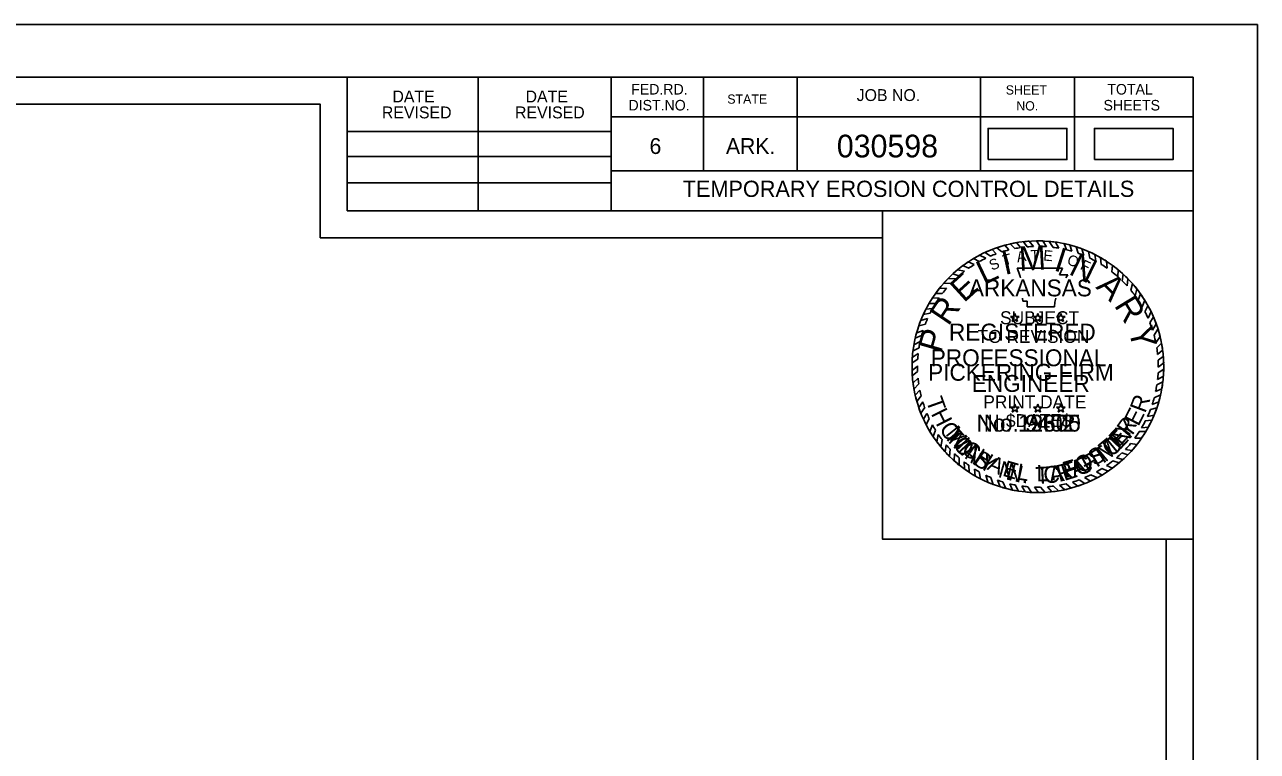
# Model space of a CAD drawing. Extents: x 814841 to 962585, y -174183 to 1802800.
# Drawn here: x 820260 to 820716.4, y 1802531 to 1802800.1 of the extents above; entities that cross this region are included whole.
import ezdxf

# ---------------------------------------------------------------- set-up
doc = ezdxf.new("R2010")
doc.units = 0
for name, color, linetype in [('R_Border', 7, 'Continuous'), ('R_Border Notes', 7, 'Continuous'), ('R_No Plot', 7, 'Continuous'), ('STAMP_PE_CRAFTON', 7, 'Continuous'), ('STAMP_PE_FOSTER', 7, 'Continuous'), ('STAMP_PE_SEAL-INFO', 7, 'Continuous'), ('STAMP_PE_TAEGTMEYER', 7, 'Continuous'), ('STAMP_PE_TXT', 7, 'Continuous'), ('STAMP_PRELIMINARY', 7, 'Continuous'), ('Veg Buffer', 7, 'Continuous')]:
    doc.layers.add(name, color=color, linetype=linetype)

msp = doc.modelspace()

# ---------------------------------------------------------------- linework, layer by layer
at = {"layer": 'R_Border'}
for p, q in [((819111.78, 1802780.6), (820692.68, 1802780.6)), ((820379.48, 1802731.2), (820379.48, 1802780.6)), ((820427.88, 1802731.2), (820427.88, 1802780.6)), ((820477.18, 1802780.6), (820477.18, 1802731.2)), ((820511.38, 1802780.6), (820511.38, 1802745.9)), ((820546.08, 1802780.6), (820546.08, 1802745.9)), ((820613.98, 1802780.6), (820613.98, 1802745.9)), ((820648.68, 1802780.6), (820648.68, 1802745.9)), ((820692.68, 1801753.3), (820692.68, 1802780.6)), ((820692.68, 1802765.9), (820477.18, 1802765.9)), ((820692.68, 1802766), (820692.68, 1802766)), ((820379.48, 1802760.5), (820477.18, 1802760.5)), ((820379.48, 1802751.2), (820477.18, 1802751.2)), ((820692.68, 1802745.9), (820477.18, 1802745.9)), ((820491.98, 1802745.9), (820692.68, 1802745.9)), ((820379.48, 1802741.5), (820477.18, 1802741.5)), ((820692.68, 1802731.2), (820379.48, 1802731.2))]:
    msp.add_line(p, q, dxfattribs=at)
at = {"layer": 'R_No Plot'}
for points in [[(819049.74, 1802800.08), (820716.44, 1802800.08), (820716.44, 1801733.39), (819049.74, 1801733.39)], [(820682.68, 1802276.95), (819121.78, 1802276.95), (819121.78, 1802770.6), (820369.48, 1802770.6), (820369.48, 1802721.2), (820457.18, 1802721.2), (820577.68, 1802721.2), (820577.68, 1802609.54), (820682.68, 1802609.54)], [(820682.68, 1802276.95), (819121.78, 1802276.95), (819121.78, 1802770.6), (820369.48, 1802770.6), (820369.48, 1802721.2), (820457.18, 1802721.2), (820577.68, 1802721.2), (820577.68, 1802609.54), (820682.68, 1802609.54)], [(820682.68, 1802276.95), (819121.78, 1802276.95), (819121.78, 1802770.6), (820369.48, 1802770.6), (820369.48, 1802721.2), (820457.18, 1802721.2), (820577.68, 1802721.2), (820577.68, 1802609.54), (820682.68, 1802609.54)], [(820682.68, 1802276.95), (819121.78, 1802276.95), (819121.78, 1802770.6), (820369.48, 1802770.6), (820369.48, 1802721.2), (820457.18, 1802721.2), (820577.68, 1802721.2), (820577.68, 1802609.54), (820682.68, 1802609.54)], [(820682.68, 1802276.95), (819121.78, 1802276.95), (819121.78, 1802770.6), (820369.48, 1802770.6), (820369.48, 1802721.2), (820457.18, 1802721.2), (820577.68, 1802721.2), (820577.68, 1802609.54), (820682.68, 1802609.54)], [(820682.68, 1802276.95), (819121.78, 1802276.95), (819121.78, 1802770.6), (820369.48, 1802770.6), (820369.48, 1802721.2), (820457.18, 1802721.2), (820577.68, 1802721.2), (820577.68, 1802609.54), (820682.68, 1802609.54)], [(819121.78, 1802770.6), (820369.48, 1802770.6), (820369.48, 1802721.2), (820457.18, 1802721.2), (820577.68, 1802721.2), (820577.68, 1802609.54), (820682.68, 1802609.54), (820682.68, 1801763.3), (819121.78, 1801763.3)], [(820682.68, 1802276.95), (819121.78, 1802276.95), (819121.78, 1802770.6), (820369.48, 1802770.6), (820369.48, 1802721.2), (820457.18, 1802721.2), (820577.68, 1802721.2), (820577.68, 1802609.54), (820682.68, 1802609.54)], [(820577.68, 1802731.2), (820692.68, 1802731.2), (820692.68, 1802609.54), (820577.68, 1802609.54)]]:
    msp.add_lwpolyline(points, close=True, dxfattribs=at)
at = {"layer": 'STAMP_PE_SEAL-INFO'}
for p, q in [((820627.28, 1802719.36), (820628.78, 1802717.52)), ((820629.86, 1802719.72), (820631.27, 1802717.81)), ((820633.54, 1802717.95), (820631.98, 1802719.92)), ((820636.03, 1802717.98), (820634.63, 1802720.03)), ((820638.32, 1802717.87), (820637.03, 1802719.99)), ((820640.85, 1802717.62), (820639.38, 1802719.84)), ((820642.97, 1802717.3), (820641.69, 1802719.57)), ((820645.79, 1802716.7), (820644.92, 1802719)), ((820613.54, 1802714.7), (820615.86, 1802713.58)), ((820615.7, 1802715.76), (820617.65, 1802714.39)), ((820618.24, 1802716.84), (820619.71, 1802715.21)), ((820619.98, 1802717.48), (820621.88, 1802715.95)), ((820622.93, 1802718.39), (820624.37, 1802716.65)), ((820624.87, 1802718.88), (820626.65, 1802717.16)), ((820647.79, 1802716.16), (820647, 1802718.51)), ((820650.05, 1802715.43), (820649.35, 1802717.82)), ((820652.14, 1802714.63), (820651.42, 1802717.11)), ((820654.45, 1802713.6), (820653.94, 1802716.09)), ((820656.68, 1802712.45), (820656.24, 1802715)), ((820607.27, 1802710.9), (820609.55, 1802709.87)), ((820609.37, 1802712.23), (820611.58, 1802711.22)), ((820611.3, 1802713.45), (820613.46, 1802712.34)), ((820627.54, 1802709.87), (820644.26, 1802709.87)), ((820628.15, 1802708.34), (820627.54, 1802709.87)), ((820644.26, 1802709.87), (820643.14, 1802707.41)), ((820658.62, 1802711.32), (820658.42, 1802713.82)), ((820660.79, 1802709.89), (820660.63, 1802712.46)), ((820662.59, 1802708.55), (820662.76, 1802710.99)), ((820601.99, 1802706.14), (820604.71, 1802705.94)), ((820603.66, 1802707.76), (820605.96, 1802707.07)), ((820605.38, 1802709.26), (820608.03, 1802708.76)), ((820628.67, 1802706.85), (820628.15, 1802708.34)), ((820628.71, 1802706.28), (820628.67, 1802706.85)), ((820643.14, 1802707.41), (820646.3, 1802707.41)), ((820646.3, 1802707.41), (820645.58, 1802706.28)), ((820664.83, 1802706.69), (820664.92, 1802709.31)), ((820666.39, 1802705.23), (820666.73, 1802707.72)), ((820668.18, 1802703.36), (820668.52, 1802705.99)), ((820598.65, 1802702.37), (820601.39, 1802702.48)), ((820600.37, 1802704.42), (820602.98, 1802704.23)), ((820669.55, 1802701.78), (820670.23, 1802704.14)), ((820671.17, 1802699.7), (820671.85, 1802702.19)), ((820594.85, 1802696.79), (820597.3, 1802696.89)), ((820596.08, 1802698.8), (820598.66, 1802698.97)), ((820597.25, 1802700.52), (820599.78, 1802700.49)), ((820629.66, 1802697.73), (820629.53, 1802698.82)), ((820631.23, 1802697.73), (820629.66, 1802697.73)), ((820631.23, 1802695.58), (820631.23, 1802697.73)), ((820641.46, 1802697.27), (820641.38, 1802695.58)), ((820641.85, 1802698.82), (820641.46, 1802697.27)), ((820672.27, 1802698.12), (820673.16, 1802700.44)), ((820673.81, 1802695.63), (820674.73, 1802698.09)), ((820592.76, 1802692.73), (820595.27, 1802693.25)), ((820593.7, 1802694.68), (820596.19, 1802695)), ((820641.38, 1802695.58), (820631.23, 1802695.58)), ((820674.81, 1802693.8), (820675.94, 1802696.02)), ((820675.96, 1802691.38), (820677.1, 1802693.81)), ((820676.67, 1802689.7), (820677.99, 1802691.86)), ((820591.09, 1802688.54), (820593.51, 1802689.22)), ((820591.84, 1802690.57), (820594.36, 1802691.3)), ((820677.64, 1802686.95), (820678.99, 1802689.32)), ((820678.18, 1802685.13), (820679.65, 1802687.39)), ((820591.6, 1802682.75), (820589.27, 1802681.51)), ((820589.78, 1802683.99), (820592.13, 1802684.95)), ((820590.3, 1802686.02), (820592.69, 1802686.87)), ((820678.84, 1802682.33), (820680.44, 1802684.57)), ((820590.88, 1802678.28), (820588.69, 1802676.88)), ((820591.17, 1802680.46), (820588.94, 1802679.35)), ((820679.19, 1802680.43), (820680.96, 1802682.2)), ((820679.52, 1802677.89), (820681.38, 1802679.57)), ((820590.7, 1802676.16), (820588.59, 1802674.87)), ((820590.61, 1802673.69), (820588.59, 1802672.01)), ((820679.68, 1802675.8), (820681.63, 1802677.26)), ((820679.75, 1802673.21), (820681.77, 1802674.82)), ((820590.65, 1802671.66), (820588.69, 1802670.03)), ((820590.81, 1802669.18), (820588.96, 1802667.4)), ((820679.49, 1802668.65), (820681.66, 1802669.93)), ((820679.69, 1802671.18), (820681.78, 1802672.57)), ((820591.07, 1802667.03), (820589.3, 1802665.17)), ((820591.46, 1802664.74), (820589.77, 1802662.9)), ((820678.79, 1802664.21), (820681.06, 1802665.19)), ((820679.24, 1802666.71), (820681.45, 1802667.81)), ((820591.93, 1802662.64), (820590.37, 1802660.57)), ((820592.55, 1802660.41), (820591.08, 1802658.32)), ((820677.51, 1802659.48), (820679.96, 1802660.48)), ((820678.25, 1802661.95), (820680.6, 1802662.96)), ((820593.26, 1802658.29), (820591.85, 1802656.23)), ((820594.09, 1802656.16), (820592.78, 1802654.05)), ((820675.77, 1802655.01), (820678.21, 1802655.49)), ((820676.84, 1802657.58), (820679.25, 1802658.23)), ((820594.95, 1802654.24), (820593.81, 1802651.94)), ((820596.12, 1802651.95), (820595.17, 1802649.5)), ((820673.6, 1802650.83), (820676.11, 1802651.1)), ((820674.96, 1802653.33), (820677.4, 1802653.67)), ((820597.3, 1802649.93), (820596.38, 1802647.58)), ((820598.31, 1802648.38), (820597.76, 1802645.62)), ((820599.71, 1802646.42), (820599.21, 1802643.77)), ((820671.04, 1802646.96), (820673.57, 1802646.97)), ((820672.74, 1802649.43), (820675.13, 1802649.4)), ((820601.23, 1802644.54), (820600.8, 1802641.94)), ((820602.75, 1802642.85), (820602.44, 1802640.24)), ((820666.31, 1802641.53), (820668.52, 1802640.84)), ((820667.59, 1802642.82), (820669.97, 1802642.4)), ((820669.5, 1802644.99), (820671.81, 1802644.59)), ((820604.36, 1802641.22), (820604.21, 1802638.58)), ((820606.08, 1802639.66), (820606.06, 1802637.01)), ((820607.88, 1802638.19), (820607.97, 1802635.56)), ((820609.57, 1802636.94), (820609.75, 1802634.35)), ((820660.63, 1802636.83), (820662.82, 1802635.88)), ((820662.93, 1802638.54), (820665.27, 1802637.82)), ((820664.29, 1802639.67), (820666.64, 1802639.02)), ((820611.71, 1802635.53), (820612.01, 1802632.97)), ((820613.46, 1802634.5), (820613.92, 1802631.93)), ((820615.87, 1802633.25), (820616.65, 1802630.64)), ((820617.73, 1802632.41), (820618.59, 1802629.85)), ((820652.5, 1802632.35), (820654.62, 1802631.05)), ((820654.8, 1802633.4), (820657.22, 1802632.34)), ((820656.84, 1802634.47), (820658.92, 1802633.3)), ((820658.91, 1802635.69), (820661.16, 1802634.71)), ((820620.19, 1802631.44), (820621.24, 1802628.94)), ((820622.24, 1802630.77), (820623.37, 1802628.32)), ((820624.78, 1802630.08), (820625.84, 1802627.75)), ((820626.77, 1802629.65), (820628, 1802627.36)), ((820629.27, 1802629.24), (820630.47, 1802627.04)), ((820631.45, 1802629), (820632.82, 1802626.86)), ((820633.87, 1802628.87), (820635.39, 1802626.8)), ((820636.17, 1802628.86), (820637.89, 1802626.88)), ((820638.77, 1802628.99), (820640.39, 1802627.09)), ((820640.96, 1802629.22), (820642.82, 1802627.43)), ((820643.18, 1802629.57), (820645.13, 1802627.88)), ((820645.64, 1802630.09), (820647.53, 1802628.47)), ((820647.94, 1802630.72), (820650.02, 1802629.23)), ((820650.41, 1802631.53), (820652.62, 1802630.19))]:
    msp.add_line(p, q, dxfattribs=at)
for radius, start, end in [(46.61, 99.7525, 102.7765), (46.61, 93.9381, 96.5517), (46.61, 87.7298, 90.6707), (46.61, 81.9732, 84.8236), (46.61, 75.3125, 77.9426), (46.61, 117.6544, 120.8099), (46.61, 111.3124, 114.7026), (44.57, 110.3086, 113.1659), (46.61, 105.2339, 109.0352), (44.57, 104.0352, 107.3615), (44.57, 98.258, 101.0329), (44.57, 92.1102, 95.0367), (44.57, 85.9628, 88.9097), (44.57, 79.9264, 82.696), (44.57, 73.5575, 76.2314), (46.61, 69.6061, 72.3058), (44.57, 67.6248, 70.504), (46.61, 63.1329, 66.2704), (46.61, 123.6199, 126.5906), (44.57, 121.9746, 125.11), (44.57, 115.6869, 119.1583), (44.57, 61.1558, 64.3784), (46.61, 56.9003, 60.0942), (44.57, 54.9238, 58.2702), (46.61, 50.3492, 53.7159), (46.61, 135.4021, 138.3031), (44.57, 133.1331, 136.2562), (46.61, 129.7326, 132.5376), (44.57, 127.5297, 130.9683), (44.57, 48.3016, 52.0395), (46.61, 44.3405, 47.3929), (46.61, 141.6056, 144.4486), (44.57, 139.301, 142.5873), (44.57, 42.2212, 45.5512), (44.57, 36.135, 39.5311), (46.61, 38.1247, 41.2316), (46.61, 147.0072, 149.899), (44.57, 145.0197, 148.2104), (44.57, 29.9032, 33.6645), (46.61, 31.9614, 35.4294), (46.61, 152.864, 155.5189), (44.57, 151.0315, 153.573), (44.57, 23.7732, 27.2211), (46.61, 25.9391, 29.0125), (46.61, 19.9538, 23.3141), (46.61, 158.4077, 161.0701), (44.57, 156.3402, 159.2319), (44.57, 17.6802, 21.4251), (46.61, 13.8421, 17.4447), (46.61, 164.3068, 166.894), (44.57, 167.9048, 170.9039), (44.57, 162.4331, 165.0013), (44.57, 11.5444, 15.2364), (46.61, 170.0003, 172.6878), (44.57, 173.73, 176.4734), (44.57, 5.7599, 9.0606), (46.61, 7.5852, 10.8621), (46.61, 175.7409, 178.2066), (44.57, 179.6454, 182.2633), (44.57, 359.7329, 3.0639), (46.61, 1.7215, 4.7268), (46.61, 181.7251, 184.1626), (44.57, 185.4539, 188.234), (44.57, 353.8632, 357.1274), (46.61, 355.7156, 358.9569), (46.61, 187.4204, 190.1927), (44.57, 191.2274, 193.9858), (44.57, 348.0778, 351.3435), (46.61, 349.8305, 353.0885), (46.61, 193.0369, 195.9973), (44.57, 196.9675, 199.8353), (44.57, 341.777, 345.0925), (46.61, 343.8925, 347.035), (46.61, 198.8967, 201.6281), (44.57, 202.7761, 205.4791), (44.57, 335.6038, 339.1858), (46.61, 337.3837, 340.9933), (46.61, 204.5479, 207.4328), (44.57, 208.7883, 211.7934), (44.57, 329.5549, 333.2076), (46.61, 331.4037, 334.9332), (46.61, 210.8636, 213.6571), (44.57, 214.1838, 217.2747), (44.57, 323.5851, 327.4407), (46.61, 325.4405, 328.9872), (46.61, 216.6115, 219.491), (46.61, 222.48, 225.3801), (44.57, 220.3909, 223.3056), (44.57, 310.7744, 314.3161), (44.57, 316.6531, 320.3711), (46.61, 318.2846, 321.8043), (46.61, 228.3665, 231.348), (44.57, 226.2494, 229.2407), (44.57, 232.229, 234.9336), (44.57, 304.823, 308.5143), (46.61, 306.3721, 310.208), (46.61, 312.4518, 315.6633), (46.61, 234.295, 236.9452), (44.57, 238.2223, 240.8353), (46.61, 240.1977, 242.8613), (44.57, 244.3204, 246.9486), (44.57, 292.8745, 296.1185), (46.61, 294.6481, 298.2166), (44.57, 299.0768, 302.1724), (46.61, 300.621, 303.8703), (46.61, 246.576, 249.1558), (44.57, 250.3491, 253.1216), (46.61, 252.5967, 255.3252), (44.57, 256.505, 259.1192), (46.61, 258.4433, 261.1398), (44.57, 262.3783, 265.2012), (44.57, 268.3215, 271.277), (44.57, 274.6157, 277.4486), (44.57, 280.3459, 283.5814), (46.61, 282.3199, 285.3702), (44.57, 286.6423, 289.9783), (46.61, 288.5709, 291.9733), (46.61, 264.1978, 267.1009), (46.61, 270.2548, 273.3361), (46.61, 276.4239, 279.4357)]:
    msp.add_arc((820635.18, 1802673.42), radius, start, end, dxfattribs=at)
at = {"layer": 'STAMP_PE_TXT'}
for p, q in [((820626.08, 1802691.27), (820625.08, 1802691.99)), ((820625.08, 1802691.99), (820626.31, 1802691.99)), ((820626.31, 1802691.99), (820626.69, 1802693.16)), ((820626.69, 1802693.16), (820627.07, 1802691.99)), ((820627.07, 1802691.99), (820628.29, 1802691.99)), ((820628.29, 1802691.99), (820627.3, 1802691.27)), ((820634.57, 1802691.27), (820633.57, 1802691.99)), ((820633.57, 1802691.99), (820634.8, 1802691.99)), ((820634.8, 1802691.99), (820635.18, 1802693.16)), ((820635.18, 1802693.16), (820635.56, 1802691.99)), ((820635.56, 1802691.99), (820636.78, 1802691.99)), ((820636.78, 1802691.99), (820635.79, 1802691.27)), ((820643.06, 1802691.27), (820642.06, 1802691.99)), ((820642.06, 1802691.99), (820643.29, 1802691.99)), ((820643.29, 1802691.99), (820643.67, 1802693.16)), ((820643.67, 1802693.16), (820644.05, 1802691.99)), ((820644.05, 1802691.99), (820645.27, 1802691.99)), ((820645.27, 1802691.99), (820644.28, 1802691.27)), ((820625.7, 1802690.11), (820626.08, 1802691.27)), ((820626.69, 1802690.83), (820625.7, 1802690.11)), ((820627.68, 1802690.11), (820626.69, 1802690.83)), ((820627.3, 1802691.27), (820627.68, 1802690.11)), ((820634.19, 1802690.11), (820634.57, 1802691.27)), ((820635.18, 1802690.83), (820634.19, 1802690.11)), ((820636.17, 1802690.11), (820635.18, 1802690.83)), ((820635.79, 1802691.27), (820636.17, 1802690.11)), ((820642.68, 1802690.11), (820643.06, 1802691.27)), ((820643.67, 1802690.83), (820642.68, 1802690.11)), ((820644.66, 1802690.11), (820643.67, 1802690.83)), ((820644.28, 1802691.27), (820644.66, 1802690.11)), ((820626.31, 1802658.46), (820626.69, 1802659.62)), ((820626.69, 1802659.62), (820627.07, 1802658.46)), ((820634.8, 1802658.46), (820635.18, 1802659.62)), ((820635.18, 1802659.62), (820635.56, 1802658.46)), ((820643.29, 1802658.46), (820643.67, 1802659.62)), ((820643.67, 1802659.62), (820644.05, 1802658.46)), ((820626.08, 1802657.74), (820625.08, 1802658.46)), ((820625.08, 1802658.46), (820626.31, 1802658.46)), ((820625.7, 1802656.57), (820626.08, 1802657.74)), ((820626.69, 1802657.29), (820625.7, 1802656.57)), ((820627.68, 1802656.57), (820626.69, 1802657.29)), ((820627.07, 1802658.46), (820628.29, 1802658.46)), ((820628.29, 1802658.46), (820627.3, 1802657.74)), ((820627.3, 1802657.74), (820627.68, 1802656.57)), ((820634.57, 1802657.74), (820633.57, 1802658.46)), ((820633.57, 1802658.46), (820634.8, 1802658.46)), ((820634.19, 1802656.57), (820634.57, 1802657.74)), ((820635.18, 1802657.29), (820634.19, 1802656.57)), ((820636.17, 1802656.57), (820635.18, 1802657.29)), ((820635.56, 1802658.46), (820636.78, 1802658.46)), ((820636.78, 1802658.46), (820635.79, 1802657.74)), ((820635.79, 1802657.74), (820636.17, 1802656.57)), ((820643.06, 1802657.74), (820642.06, 1802658.46)), ((820642.06, 1802658.46), (820643.29, 1802658.46)), ((820642.68, 1802656.57), (820643.06, 1802657.74)), ((820643.67, 1802657.29), (820642.68, 1802656.57)), ((820644.66, 1802656.57), (820643.67, 1802657.29)), ((820644.05, 1802658.46), (820645.27, 1802658.46)), ((820645.27, 1802658.46), (820644.28, 1802657.74)), ((820644.28, 1802657.74), (820644.66, 1802656.57))]:
    msp.add_line(p, q, dxfattribs=at)
at = {"layer": 'STAMP_PRELIMINARY'}
msp.add_circle((820635.18, 1802673.42), 46.61, dxfattribs=at)
at = {"layer": 'Veg Buffer'}
for points in [[(820616.75, 1802750.13), (820645.91, 1802750.13), (820645.91, 1802761.68), (820616.75, 1802761.68)], [(820656.1, 1802750.13), (820685.26, 1802750.13), (820685.26, 1802761.68), (820656.1, 1802761.68)]]:
    msp.add_lwpolyline(points, close=True, dxfattribs=at)

# ---------------------------------------------------------------- texts
at = {"layer": 'R_Border'}
for s, height, p in [('DATE', 4.396, (820396.17, 1802771.28)), ('DATE', 4.396, (820445.47, 1802771.28)), ('FED.RD.', 3.91, (820484.58, 1802774.2)), ('STATE', 3.42, (820520.18, 1802770.8)), ('JOB NO.', 4.396, (820568.08, 1802771.8)), ('SHEET', 3.42, (820623.28, 1802774.2)), ('TOTAL', 3.91, (820660.88, 1802774.2)), ('REVISED', 4.396, (820392.27, 1802765.38)), ('REVISED', 4.396, (820441.57, 1802765.38)), ('DIST.NO.', 3.91, (820483.58, 1802768.3)), ('NO.', 3.42, (820627.18, 1802768.3)), ('SHEETS', 3.91, (820659.48, 1802768.3)), ('6', 5.86, (820491.38, 1802752.2)), ('ARK.', 5.861, (820519.68, 1802752.2))]:
    msp.add_text(s, height=height, dxfattribs=at).set_placement(p)
at = {"layer": 'R_Border Notes'}
for s, height, p in [('030598', 8.4, (820560.73, 1802750.93)), ('TEMPORARY EROSION CONTROL DETAILS', 6, (820503.68, 1802736.3))]:
    msp.add_text(s, height=height, dxfattribs=at).set_placement(p)
at = {"layer": 'STAMP_PE_CRAFTON'}
msp.add_text('No. 12370', height=6.25, dxfattribs=at).set_placement((820612.49, 1802649.4))
for s, rotation, p in [('T', 310.7442, (820600.01, 1802647.9)), ('N', 49.2411, (820666.59, 1802643.53)), ('O', 317.6422, (820603.34, 1802643.85)), ('O', 41.8391, (820662.35, 1802639.62)), ('N', 324.4537, (820607.57, 1802639.92)), ('Y', 331.1686, (820612.74, 1802636.34)), ('F', 28.7821, (820653.48, 1802634.06)), ('T', 34.1136, (820658.06, 1802636.61)), ('N', 347.4752, (820623.01, 1802631.76)), ('C', 6.0117, (820637.54, 1802630.12)), ('R', 14.8189, (820643.02, 1802630.7)), ('A', 20.5125, (820648.58, 1802632.19)), ('.', 356.8926, (820629.16, 1802630.38))]:
    msp.add_text(s, height=6.25, rotation=rotation, dxfattribs=at).set_placement(p)
at = {"layer": 'STAMP_PE_FOSTER'}
msp.add_text('No. 9402', height=6.25, dxfattribs=at).set_placement((820615.11, 1802649.4))
for s, rotation, p in [('M', 308.339, (820600.76, 1802648.53)), ('E', 46.9613, (820665.18, 1802643.37)), ('R', 54.5031, (820668.8, 1802647.47)), ('I', 314.1842, (820604.75, 1802643.84)), ('T', 39.4194, (820660.89, 1802639.62)), ('C', 319.8733, (820606.52, 1802642.07)), ('H', 327.7235, (820611.16, 1802638.39)), ('S', 31.7234, (820656.13, 1802636.48)), ('A', 335.7276, (820616.07, 1802635.48)), ('E', 343.5779, (820621.76, 1802633.13)), ('L', 350.8115, (820627.05, 1802631.74)), ('L', 1.2666, (820634.75, 1802630.96)), ('F', 15.8691, (820645.35, 1802632.19)), ('O', 23.719, (820650.58, 1802633.83)), ('.', 6.8035, (820639.98, 1802631.25))]:
    msp.add_text(s, height=6, rotation=rotation, dxfattribs=at).set_placement(p)
at = {"layer": 'STAMP_PE_TAEGTMEYER'}
for s, rotation, p in [('T', 289.646, (820593.65, 1802660.97)), ('R', 69.57, (820674.9, 1802655.99)), ('H', 296.7339, (820595.45, 1802656.04)), ('E', 63.0984, (820672.41, 1802651.08)), ('O', 303.7708, (820598.41, 1802650.5)), ('Y', 53.9986, (820669.07, 1802646.38)), ('M', 314.2033, (820601.69, 1802645.75)), ('M', 39.3, (820660.17, 1802637.91)), ('E', 46.8094, (820665.37, 1802642.3)), ('A', 321.0594, (820606.5, 1802640.93)), ('S', 327.8239, (820610.63, 1802637.71)), ('T', 31.466, (820655.68, 1802635.19)), ('N', 344.2727, (820620.11, 1802632.67)), ('A', 8.9826, (820639.73, 1802630.3)), ('E', 17.6836, (820644.93, 1802631.07)), ('G', 23.3052, (820650.18, 1802632.73)), ('T', 3.0061, (820634.5, 1802630.02)), ('.', 350.6464, (820626.18, 1802631.01))]:
    msp.add_text(s, height=6.25, rotation=rotation, dxfattribs=at).set_placement(p)
msp.add_text('No. 19605', height=6.25, dxfattribs=at).set_placement((820612.49, 1802649.4))
at = {"layer": 'STAMP_PE_TXT'}
for s, rotation, p in [('T', 16.311, (820622.79, 1802710.8)), ('A', 9.0679, (820627.6, 1802712.06)), ('T', 1.8248, (820632.53, 1802712.71)), ('E', 355.2002, (820637.08, 1802712.75)), ('O', 342.2506, (820645.72, 1802711.37)), ('S', 23.5541, (820618.17, 1802708.93)), ('F', 335.0075, (820650.54, 1802709.68))]:
    msp.add_text(s, height=3.91, rotation=rotation, dxfattribs=at).set_placement(p)
for s, p in [('ARKANSAS', (820609.64, 1802699.47)), ('REGISTERED', (820602.26, 1802683.12)), ('PROFESSIONAL', (820595.52, 1802673.61)), ('ENGINEER', (820610.72, 1802664.11))]:
    msp.add_text(s, height=6.25, dxfattribs=at).set_placement(p)
at = {"layer": 'STAMP_PRELIMINARY'}
for s, rotation, p in [('I', 12.5248, (820622.87, 1802707.35)), ('M', 3.1074, (820628.36, 1802708.89)), ('I', 342.3164, (820640.7, 1802709.23)), ('N', 333.9382, (820646.23, 1802707.86)), ('L', 25.513, (820615.22, 1802703.55)), ('E', 42.3578, (820607.81, 1802696.9)), ('A', 315.6579, (820656.4, 1802702.73)), ('R', 56.2292, (820602.03, 1802688.23)), ('R', 301.3831, (820663.24, 1802696.16)), ('P', 73.913, (820599.29, 1802678.12)), ('Y', 283.2593, (820668.69, 1802687.23))]:
    msp.add_text(s, height=9, rotation=rotation, dxfattribs=at).set_placement(p)
for s, height, p in [('SUBJECT', 4.8, (820621.18, 1802689.16)), ('TO REVISION', 4.8, (820612.86, 1802682.24)), ('PICKERING FIRM', 6.25, (820594.55, 1802668.23)), ('PRINT DATE', 4.8, (820614.97, 1802657.99)), ('$DATE$', 4.8, (820623.35, 1802651.07))]:
    msp.add_text(s, height=height, dxfattribs=at).set_placement(p)

doc.saveas('drawing.dxf')
